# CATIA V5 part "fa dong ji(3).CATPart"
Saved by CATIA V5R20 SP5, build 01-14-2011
Part number: 发动机
Bounding box of the stored display mesh (mm): x -40 to 40, y -40 to 40, z -5 to 135
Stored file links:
  E:\姜浩然03.08\创意作品\fa dong ji(3).CATPart
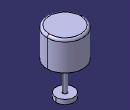
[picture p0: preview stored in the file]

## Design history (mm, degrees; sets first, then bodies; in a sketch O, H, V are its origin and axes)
Body1 (main body)
  Sketch1 on xy-plane, origin (0, 0, 0), H (1, 0, 0), V (0, 1, 0)
    circle A1 centre (0, 0) radius 20
  Pad1: profile Sketch1, direction (0, 0, 1), length 5, mirrored extent
  Sketch2 on xy-plane, origin (0, 0, 0), H (1, 0, 0), V (0, 1, 0)
    circle A1 centre (0, 0) radius 5
    point P1 (5, 0)
    coincidence: A1 P1, P1 H
  Pad2: profile Sketch2, direction (0, 0, 1), length 75
  Plane1: type Offset, RefPlane xy-plane, Offset 70
Body2
  Sketch3 on Plane1, origin (0, 0, 70), H (1, 0, 0), V (0, 1, 0)
    circle A1 centre (0, 0) radius 40
  Pad3: profile Sketch3, direction (0, 0, 1), length 45
  ThickSurface1: BotOffset 20, Surface end face of Pad3, TopOffset 20
  Fillet1: radius 5, on face of ThickSurface1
